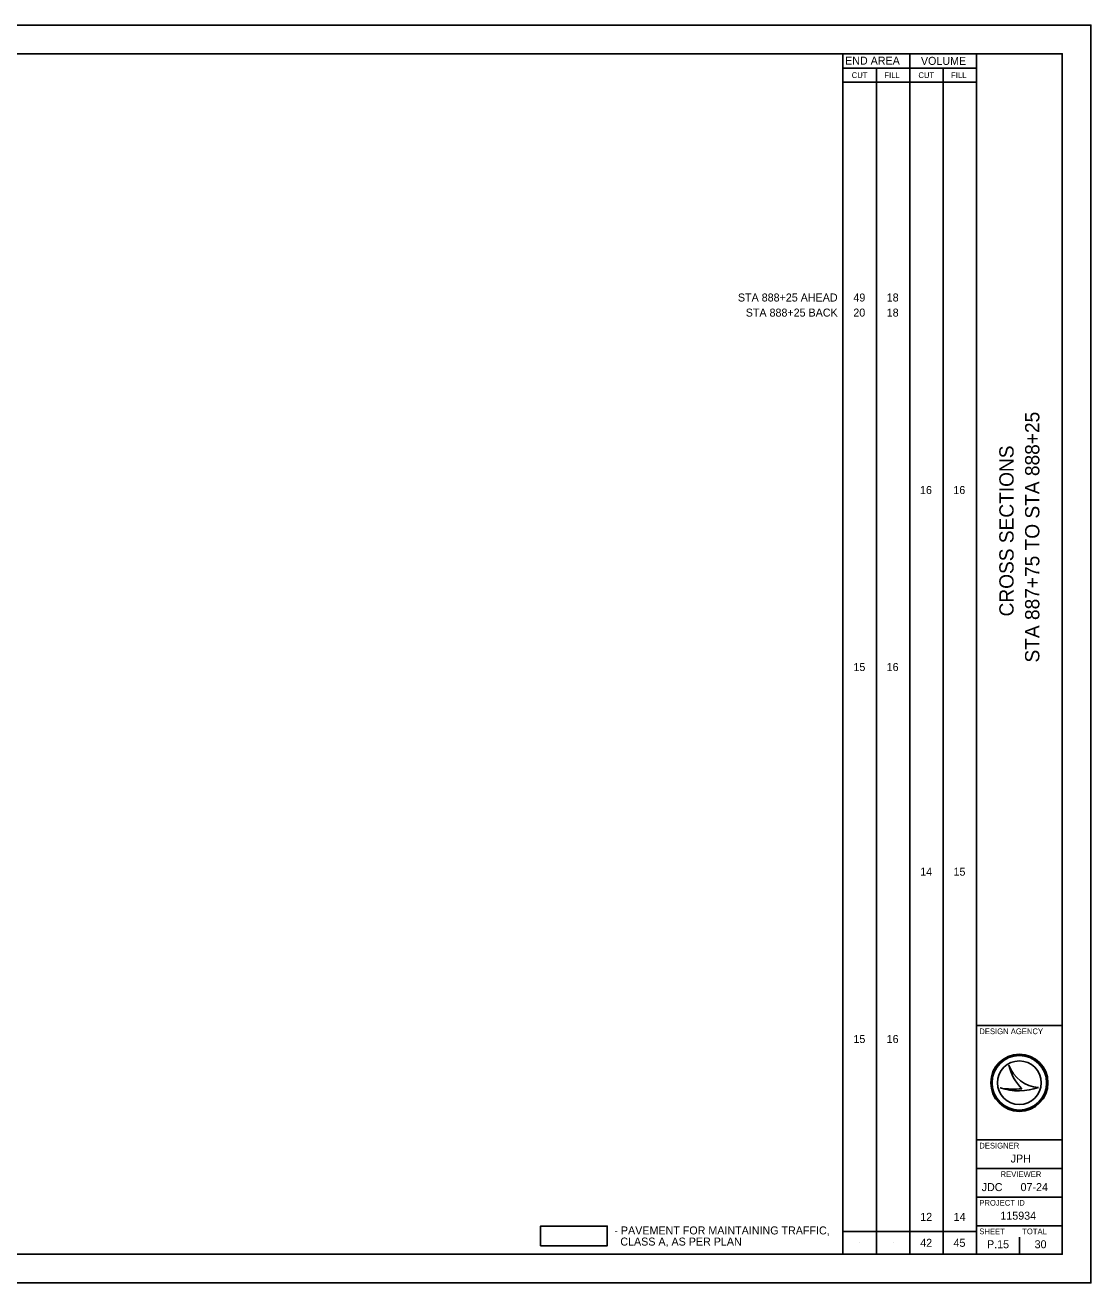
# Model space of a CAD drawing. Extents: x -165 to 34, y -83 to 22.
# Drawn here: x 15.37 to 34, y 0 to 22 of the extents above; entities that cross this region are included whole.
import ezdxf

# ---------------------------------------------------------------- set-up
doc = ezdxf.new("R2010")
doc.units = 0
for name, color, linetype in [('PV_X_Shoulder_Aggregate', 7, 'Continuous'), ('SH_Border', 7, 'Continuous'), ('SH_Cut_Line', 7, 'Continuous'), ('SH_Data', 7, 'Continuous'), ('VG_X_Cells', 7, 'Continuous')]:
    doc.layers.add(name, color=color, linetype=linetype)

msp = doc.modelspace()

# ---------------------------------------------------------------- linework, layer by layer
at = {"layer": 'SH_Border'}
for p, q in [((32, 0.5), (32, 21.5)), ((32, 4.5), (33.5, 4.5)), ((32, 2.5), (33.5, 2.5)), ((32, 2), (33.5, 2)), ((32, 1.5), (33.5, 1.5)), ((32, 1), (33.5, 1))]:
    msp.add_line(p, q, dxfattribs=at)
msp.add_lwpolyline([(1.5, 21.5), (33.5, 21.5), (33.5, 0.5), (1.5, 0.5)], close=True, dxfattribs=at)
at = {"layer": 'SH_Cut_Line'}
msp.add_lwpolyline([(0, 0), (34, 0), (34, 22), (0, 22)], close=True, dxfattribs=at)
at = {"layer": 'SH_Data'}
for p, q in [((29.666, 0.5), (29.666, 21.5)), ((30.833, 0.5), (30.833, 21.5)), ((29.666, 21.25), (32, 21.25)), ((30.25, 0.5), (30.25, 21.25)), ((31.417, 0.5), (31.417, 21.25)), ((29.666, 21), (32, 21)), ((32.567, 3.81), (32.567, 3.81)), ((32.417, 3.41), (32.417, 3.41)), ((32.75, 3.5), (32.75, 3.5)), ((33.087, 3.419), (33.087, 3.419)), ((29.666, 0.9), (32, 0.9)), ((29.958, 0.7), (29.958, 0.7)), ((30.542, 0.7), (30.542, 0.7)), ((31.125, 0.7), (31.125, 0.7)), ((31.708, 0.7), (31.708, 0.7)), ((32.375, 0.675), (32.375, 0.675)), ((32.75, 0.5), (32.75, 0.8))]:
    msp.add_line(p, q, dxfattribs=at)
for radius in [0.5, 0.477, 0.477, 0.382]:
    msp.add_circle((32.75, 3.5), radius, dxfattribs=at)
for centre, radius, start, end in [((33.116, 3.998), 0.58, 198.9257, 198.9319), ((33.347, 3.97), 0.796, 191.6379, 191.6421), ((33.116, 3.998), 0.58, 198.9319, 267.1657), ((33.347, 3.97), 0.796, 191.6421, 226.0947), ((32.739, 4.37), 1.013, 251.4576, 290.0832), ((32.648, 4.654), 1.266, 259.4964, 259.4995), ((32.739, 4.37), 1.013, 251.4527, 251.4576), ((32.648, 4.654), 1.266, 259.4995, 276.6672)]:
    msp.add_arc(centre, radius, start, end, dxfattribs=at)
at = {"layer": 'VG_X_Cells'}
for points in [[(24.38, 0.993), (25.544, 0.993), (25.544, 0.65), (24.38, 0.65)], [(24.38, 0.65), (25.544, 0.65), (25.544, 0.993), (24.38, 0.993), (24.38, 0.65)]]:
    msp.add_lwpolyline(points, close=True, dxfattribs=at)

# ---------------------------------------------------------------- texts
at = {"layer": 'PV_X_Shoulder_Aggregate'}
for s, p in [('STA 888+25 AHEAD', (27.829, 17.166)), ('49', (29.848, 17.166)), ('18', (30.431, 17.166)), ('STA 888+25 BACK', (27.966, 16.902)), ('20', (29.847, 16.902)), ('18', (30.431, 16.902)), ('16', (31.013, 13.798)), ('16', (31.596, 13.798)), ('15', (29.849, 10.702)), ('16', (30.43, 10.702)), ('14', (31.017, 7.122)), ('15', (31.599, 7.122)), ('15', (29.849, 4.195)), ('16', (30.43, 4.195)), ('12', (31.017, 1.084)), ('14', (31.601, 1.084)), ('- PAVEMENT FOR MAINTAINING TRAFFIC,', (25.669, 0.847)), ('  CLASS A, AS PER PLAN', (25.669, 0.652)), ('42', (31.017, 0.63)), ('45', (31.599, 0.63))]:
    msp.add_text(s, height=0.14, dxfattribs=at).set_placement(p)
at = {"layer": 'SH_Data'}
for s, height, p in [('END AREA', 0.14, (29.703, 21.309)), ('VOLUME', 0.14, (31.029, 21.305)), ('CUT', 0.1, (29.819, 21.075)), ('FILL', 0.1, (30.391, 21.075)), ('CUT', 0.1, (30.985, 21.075)), ('FILL', 0.1, (31.557, 21.075)), ('DESIGN AGENCY', 0.1, (32.05, 4.35)), ('DESIGNER', 0.1, (32.05, 2.35)), ('JPH', 0.14, (32.598, 2.105)), ('REVIEWER', 0.1, (32.422, 1.85)), ('JDC', 0.14, (32.091, 1.605)), ('07-24', 0.14, (32.771, 1.605)), ('PROJECT ID', 0.1, (32.05, 1.35)), ('115934', 0.14, (32.418, 1.105)), ('SHEET', 0.1, (32.05, 0.85)), ('TOTAL', 0.1, (32.8, 0.85)), ('P.15', 0.14, (32.185, 0.605)), ('30', 0.14, (33.017, 0.605))]:
    msp.add_text(s, height=height, dxfattribs=at).set_placement(p)
for s, p in [('STA 887+75 TO STA 888+25', (33.1, 10.851)), ('CROSS SECTIONS', (32.65, 11.657))]:
    msp.add_text(s, height=0.25, rotation=90, dxfattribs=at).set_placement(p)

doc.saveas('drawing.dxf')
